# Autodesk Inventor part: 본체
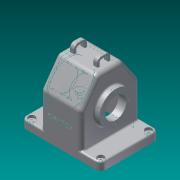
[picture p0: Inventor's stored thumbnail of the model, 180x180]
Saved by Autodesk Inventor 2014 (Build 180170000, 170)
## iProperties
Created: 2016-12
Part Number: 본체
Material: 알루미늄 6061
Document SubType Name: Modeling
Designer: net
Density: 2.71 g/cm^3
Appearance: 알루미늄 - 평지
Author: net
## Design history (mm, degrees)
sketch "스케치1"
  geometry: L1 (75, 55)-(-75, 55); L2 (-75, 55)-(-75, -55); L3 (-75, -55)-(75, -55); L4 (75, -55)-(75, 55); L5 (75, 55)-(-75, -55); L6 (-75, 55)-(75, -55); 1 further point
  constraints: 12 end point, 2 midpoint, 2 parallel, 1 horizontal, 1 perpendicular
  dimensions: "d0" = 150 distance of L1.start L1.end; "d1" = 110 distance of L3.end L1.start
extrude "돌출1" new body sketch "스케치1" distance "d2" = 15; taper "d3" = 0 deg
sketch "스케치2"
  geometry: L1 (-55, 15)-(-55, 80); L2 (55, 15)-(-55, 15) reference; L3 (-55, 80)-(-23.491, 125); L4 (-23.491, 125)-(23.491, 125); L5 (23.491, 125)-(55, 80); L6 (55, 80)-(55, 15); L7 (0, 0)-(0, 97)
  constraints: 12 end point, 2 parallel, 2 perpendicular
  dimensions: "d4" = 125 distance from line of L7.start L4; "d7" = 35 deg angle of L5 L6; "d8" = 80 vertical distance of L7.start L5.end; "d9" = 35 deg angle of L3 L1; "d10" = 80 vertical distance of L7.start L1.end
extrude "돌출2" join sketch "스케치2" stored distance "d11" = 77; taper "d12" = 0 deg
sketch "스케치3"
  geometry: L1 (-55, 80)-(-23.491, 125) reference; L2 (-23.491, 125)-(23.491, 125) reference; L3 (23.491, 125)-(55, 80) reference; L4 (55, 80)-(55, 15) reference; L5 (-55, 15)-(-55, 80) reference; L6 (50, 0)-(50, 78.424); L7 (50, 78.424)-(20.888, 120); L8 (20.888, 120)-(-20.888, 120); L9 (-20.888, 120)-(-50, 78.424); L10 (-50, 78.424)-(-50, 0); L11 (55, 0)-(-55, 0) reference; 1 further point
  constraints: 10 end point, 2 point on line, 2 other
  dimensions: "d13" = 5 distance between parallel lines of L1 L9
extrude "돌출3" cut sketch "스케치3" stored distance "d14" = 67; taper "d15" = 0 deg
sketch "스케치4"
  geometry: L1 (0, -55)-(0, 55) reference; C1 r 31 at (-65, 0); 1 further point
  constraints: 1 centre point
  dimensions: "d16" = 62 diameter of C1; "d17" = 65 distance from line of C1.centre L1
extrude "돌출4" join sketch "스케치4" distance "d18" = 10; taper "d19" = 0 deg
sketch "스케치5"
  geometry: C1 r 31 at (65, 0) reference; C2 r 37.5 at (65, 0); 1 further point
  constraints: 1 centre point, 1 coincident
  dimensions: "d20" = 75 diameter of C2
extrude "돌출5" join sketch "스케치5" distance "d21" = 5; taper "d22" = 0 deg
sketch "스케치6"
  geometry: L1 (33.5, 78.424)-(33.5, 0) reference; L2 (43.5, 27.5)-(43.5, 102.5) reference; L3 (33.5, 120)-(33.5, 78.424) reference; L4 (-33.5, 78.424)-(-33.5, 120) reference; L5 (-33.5, 0)-(-33.5, 78.424) reference; L6 (-48.5, 96)-(-48.5, 34) reference; L7 (67, 65)-(-75, 65); L8 (43.5, 65)-(19.5, 65); L9 (19.5, 92)-(33.5, 106); L10 (19.5, 92)-(19.5, 65); L11 (33.5, 78.424)-(-33.5, 78.424) reference; L12 (43.5, 102.5)-(38.5, 102.5); L13 (38.5, 102.5)-(38.5, 27.5) reference; L14 (38.5, 102.5)-(43.5, 102.5) reference; L15 (38.5, 125)-(38.5, 80) reference; L16 (38.5, 106)-(33.5, 106); 1 further point
  constraints: 13 end point, 5 point on line, 3 perpendicular, 1 midpoint
  dimensions: "d23" = 65 distance from line of point (0, 0) L7; "d24" = 27 distance from line of L7 L9.start; "d25" = 45 deg angle of L10 L9; "d26" = 24 distance between parallel lines of L10 L2
revolve "회전1" sketch "스케치6" stored, may be unused: angle "d27" = 90 deg
sketch "스케치7"
  geometry: C1 r 31 at (0, 0) reference; C2 r 20 at (0, 0); 1 further point
  constraints: 1 centre point, 1 coincident
  dimensions: "d28" = 40 diameter of C2
extrude "돌출6" cut sketch "스케치7" stored distance "d29" = 5; taper "d30" = 0 deg
node "작업 평면1"
sketch "스케치8"
  geometry: L1 (-23.491, 125)-(23.491, 125) reference; L2 (-55, 80)-(-23.491, 125) reference; L3 (23.491, 125)-(55, 80) reference; L4 (-12.5, 125)-(-12.5, 140); L5 (-12.5, 140)-(12.5, 140); L6 (12.5, 140)-(12.5, 125); L7 (7.5, 135)-(-7.5, 135); L8 (50, 0)-(-50, 0) reference; L9 (-7.5, 135)-(-7.5, 125); L10 (7.5, 135)-(7.5, 125); L11 (0, 0)-(0, 125)
  constraints: 14 end point, 4 perpendicular, 4 point on line, 1 midpoint, 1 parallel, 2 other
  dimensions: "d33" = 25 distance between parallel lines of L6 L4; "d34" = 140 distance between parallel lines of L5 L8; "d36" = 15 distance of L7.start L7.end; "d37" = 5 distance between parallel lines of L5 L7
extrude "돌출7" join sketch "스케치8" distance "d38" = 8; taper "d39" = 0 deg
fillet "모깎기1" dims "d40" = 8
fillet "모깎기2" dims "d41" = 8
fillet "모깎기3" dims "d42" = 3
fillet "모깎기4" dims "d43" = 1
fillet "모깎기5" dims "d44" = 1
fillet "모깎기6" dims "d45" = 3
fillet "모깎기7" dims "d46" = 10
fillet "모깎기8" dims "d47" = 3
fillet "모깎기9" dims "d48" = 3
sketch "스케치9" dims "d49" = 52
  geometry: C1 r 31 at (0, 0) reference; 3 further points
  constraints: 1 coincident, 1 horizontal alignment, 2 other
hole "구멍1" sketch "스케치9" at (-26, 0) diameter "d50" = 2.459; stored, may be unused: countersink angle "d54" = 90 deg, drill point angle "d56" = 118 deg; dims "d51" = 6, "d52" = 4, "d53" = 2, "d55" = 8
sketch "스케치10" dims "d60" = 58
  geometry: C1 r 20 at (0, 0) reference; 3 further points
  constraints: 1 coincident, 1 horizontal alignment, 2 other
hole "구멍2" sketch "스케치10" at (29, 0) diameter "d61" = 2.459; stored, may be unused: countersink angle "d65" = 90 deg, drill point angle "d67" = 118 deg; dims "d62" = 6, "d63" = 4, "d64" = 2, "d66" = 8
fillet "모깎기10" dims "d71" = 10
hole "구멍3" diameter "d74" = 5; stored, may be unused: countersink angle "d78" = 90 deg, drill point angle "d80" = 118 deg; dims "d72" = 10, "d73" = 10, "d75" = 6, "d76" = 12, "d77" = 5, "d79" = 20
fillet "모깎기11" dims "d81" = 3
fillet "모깎기12" dims "d82" = 3
sketch "스케치11" dims "d8" = 80
  geometry: L1 (-8, 0)-(-8, -58.847) reference; 2 further points
  constraints: 1 other
  dimensions: "d83" = 45 distance of point (30.5, -76.847) point (30.5, -31.847); "d84" = 38.5 distance from line of L1 point (30.5, -31.847)
feature "엠보싱1" sketch "스케치11" dims "d8" = 80, "d14" = 67, "d34" = 140, "d68" = 40, "d85" = 0.5, "d86" = 0
node "솔리드1"
mirror "대칭1"
pattern_circular "원형 패턴1" dims angle "d58" = 360 deg
pattern_circular "원형 패턴2" dims angle "d69" = 360 deg
mirror "대칭2"
mirror "대칭3"
node "작업 평면2"
other parameters: "d31" = 18
